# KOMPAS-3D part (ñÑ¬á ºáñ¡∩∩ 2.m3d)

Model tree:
1. Эскиз:1
2. Операция выдавливания:1
     Расстояние 1 = 0.6
3. Эскиз:2
4. Вырезать элемент выдавливания:1
     Толщина стенки 1 = 3; Толщина стенки 2 = 3; Расстояние 1 = 10
5. Эскиз:3
6. Вырезать элемент выдавливания:2
     Толщина стенки 1 = 3; Толщина стенки 2 = 3; Расстояние 1 = 10
7. Эскиз:4
8. Вырезать элемент выдавливания:3
     Толщина стенки 1 = 3; Толщина стенки 2 = 3; Расстояние 1 = 10
9. Эскиз:5
10. Вырезать элемент выдавливания:4
     Толщина стенки 1 = 3; Толщина стенки 2 = 3; Расстояние 1 = 10
